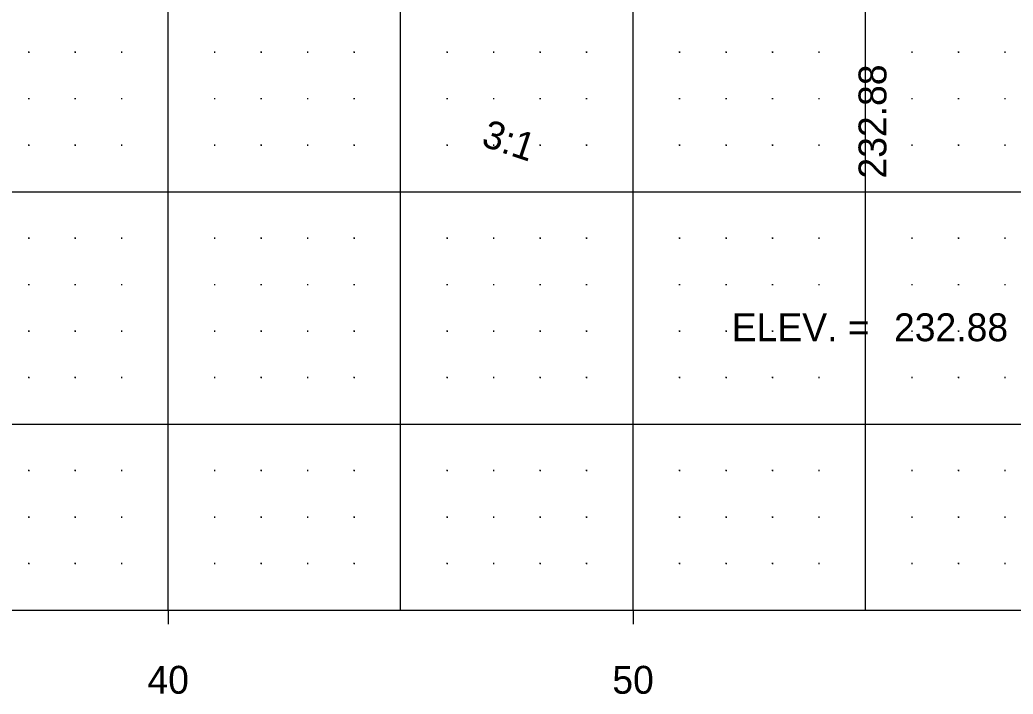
# Model space of a CAD drawing. Extents: x -80 to 80, y 222 to 253.
# Drawn here: x 36.81 to 58.18, y 224.19 to 238.7 of the extents above; entities that cross this region are included whole.
import ezdxf

# ---------------------------------------------------------------- set-up
doc = ezdxf.new("R2010")
doc.units = 0
for name, color, linetype in [('DSN_DRFT_XS Border Grid', 7, 'Continuous'), ('DSN_DRFT_XS Grid Annotations', 7, 'Continuous'), ('DSN_DRFT_XS Grid Major', 7, 'Continuous'), ('DSN_DRFT_XS Grid Minor', 7, 'Continuous'), ('DSN_RDWY_XS Annotation', 7, 'Continuous')]:
    doc.layers.add(name, color=color, linetype=linetype)

msp = doc.modelspace()

# ---------------------------------------------------------------- linework, layer by layer
at = {"layer": 'DSN_DRFT_XS Border Grid'}
msp.add_line((-77.5, 226), (77.5, 226), dxfattribs=at)
at = {"layer": 'DSN_DRFT_XS Grid Major'}
for p, q in [((40, 226), (40, 250.573)), ((45, 226), (45, 250.573)), ((50, 226), (50, 250.573)), ((55, 226), (55, 250.573)), ((-77.5, 235), (77.5, 235)), ((-77.5, 230), (77.5, 230)), ((40, 226), (40, 225.7)), ((50, 226), (50, 225.7))]:
    msp.add_line(p, q, dxfattribs=at)
at = {"layer": 'DSN_DRFT_XS Grid Minor'}
for p, q in [((37.012, 238), (36.988, 238)), ((37, 238.012), (37, 237.988)), ((38.012, 238), (37.988, 238)), ((38, 238.012), (38, 237.988)), ((39.012, 238), (38.988, 238)), ((39, 238.012), (39, 237.988)), ((41.012, 238), (40.988, 238)), ((41, 238.012), (41, 237.988)), ((42.012, 238), (41.988, 238)), ((42, 238.012), (42, 237.988)), ((43.012, 238), (42.988, 238)), ((43, 238.012), (43, 237.988)), ((44.012, 238), (43.988, 238)), ((44, 238.012), (44, 237.988)), ((46.012, 238), (45.988, 238)), ((46, 238.012), (46, 237.988)), ((47.012, 238), (46.988, 238)), ((47, 238.012), (47, 237.988)), ((48.012, 238), (47.988, 238)), ((48, 238.012), (48, 237.988)), ((49.012, 238), (48.988, 238)), ((49, 238.012), (49, 237.988)), ((51.012, 238), (50.988, 238)), ((51, 238.012), (51, 237.988)), ((52.012, 238), (51.988, 238)), ((52, 238.012), (52, 237.988)), ((53.012, 238), (52.988, 238)), ((53, 238.012), (53, 237.988)), ((54.012, 238), (53.988, 238)), ((54, 238.012), (54, 237.988)), ((56.012, 238), (55.988, 238)), ((56, 238.012), (56, 237.988)), ((57.012, 238), (56.988, 238)), ((57, 238.012), (57, 237.988)), ((58.012, 238), (57.988, 238)), ((58, 238.012), (58, 237.988)), ((37.012, 237), (36.988, 237)), ((37, 237.012), (37, 236.988)), ((38.012, 237), (37.988, 237)), ((38, 237.012), (38, 236.988)), ((39.012, 237), (38.988, 237)), ((39, 237.012), (39, 236.988)), ((41.012, 237), (40.988, 237)), ((41, 237.012), (41, 236.988)), ((42.012, 237), (41.988, 237)), ((42, 237.012), (42, 236.988)), ((43.012, 237), (42.988, 237)), ((43, 237.012), (43, 236.988)), ((44.012, 237), (43.988, 237)), ((44, 237.012), (44, 236.988)), ((46.012, 237), (45.988, 237)), ((46, 237.012), (46, 236.988)), ((47.012, 237), (46.988, 237)), ((47, 237.012), (47, 236.988)), ((48.012, 237), (47.988, 237)), ((48, 237.012), (48, 236.988)), ((49.012, 237), (48.988, 237)), ((49, 237.012), (49, 236.988)), ((51.012, 237), (50.988, 237)), ((51, 237.012), (51, 236.988)), ((52.012, 237), (51.988, 237)), ((52, 237.012), (52, 236.988)), ((53.012, 237), (52.988, 237)), ((53, 237.012), (53, 236.988)), ((54.012, 237), (53.988, 237)), ((54, 237.012), (54, 236.988)), ((56.012, 237), (55.988, 237)), ((56, 237.012), (56, 236.988)), ((57.012, 237), (56.988, 237)), ((57, 237.012), (57, 236.988)), ((58.012, 237), (57.988, 237)), ((58, 237.012), (58, 236.988)), ((37.012, 236), (36.988, 236)), ((37, 236.012), (37, 235.988)), ((38.012, 236), (37.988, 236)), ((38, 236.012), (38, 235.988)), ((39.012, 236), (38.988, 236)), ((39, 236.012), (39, 235.988)), ((41.012, 236), (40.988, 236)), ((41, 236.012), (41, 235.988)), ((42.012, 236), (41.988, 236)), ((42, 236.012), (42, 235.988)), ((43.012, 236), (42.988, 236)), ((43, 236.012), (43, 235.988)), ((44.012, 236), (43.988, 236)), ((44, 236.012), (44, 235.988)), ((46.012, 236), (45.988, 236)), ((46, 236.012), (46, 235.988)), ((47.012, 236), (46.988, 236)), ((47, 236.012), (47, 235.988)), ((48.012, 236), (47.988, 236)), ((48, 236.012), (48, 235.988)), ((49.012, 236), (48.988, 236)), ((49, 236.012), (49, 235.988)), ((51.012, 236), (50.988, 236)), ((51, 236.012), (51, 235.988)), ((52.012, 236), (51.988, 236)), ((52, 236.012), (52, 235.988)), ((53.012, 236), (52.988, 236)), ((53, 236.012), (53, 235.988)), ((54.012, 236), (53.988, 236)), ((54, 236.012), (54, 235.988)), ((56.012, 236), (55.988, 236)), ((56, 236.012), (56, 235.988)), ((57.012, 236), (56.988, 236)), ((57, 236.012), (57, 235.988)), ((58.012, 236), (57.988, 236)), ((58, 236.012), (58, 235.988)), ((37.012, 234), (36.988, 234)), ((37, 234.012), (37, 233.988)), ((38.012, 234), (37.988, 234)), ((38, 234.012), (38, 233.988)), ((39.012, 234), (38.988, 234)), ((39, 234.012), (39, 233.988)), ((41.012, 234), (40.988, 234)), ((41, 234.012), (41, 233.988)), ((42.012, 234), (41.988, 234)), ((42, 234.012), (42, 233.988)), ((43.012, 234), (42.988, 234)), ((43, 234.012), (43, 233.988)), ((44.012, 234), (43.988, 234)), ((44, 234.012), (44, 233.988)), ((46.012, 234), (45.988, 234)), ((46, 234.012), (46, 233.988)), ((47.012, 234), (46.988, 234)), ((47, 234.012), (47, 233.988)), ((48.012, 234), (47.988, 234)), ((48, 234.012), (48, 233.988)), ((49.012, 234), (48.988, 234)), ((49, 234.012), (49, 233.988)), ((51.012, 234), (50.988, 234)), ((51, 234.012), (51, 233.988)), ((52.012, 234), (51.988, 234)), ((52, 234.012), (52, 233.988)), ((53.012, 234), (52.988, 234)), ((53, 234.012), (53, 233.988)), ((54.012, 234), (53.988, 234)), ((54, 234.012), (54, 233.988)), ((56.012, 234), (55.988, 234)), ((56, 234.012), (56, 233.988)), ((57.012, 234), (56.988, 234)), ((57, 234.012), (57, 233.988)), ((58.012, 234), (57.988, 234)), ((58, 234.012), (58, 233.988)), ((37.012, 233), (36.988, 233)), ((37, 233.012), (37, 232.988)), ((38.012, 233), (37.988, 233)), ((38, 233.012), (38, 232.988)), ((39.012, 233), (38.988, 233)), ((39, 233.012), (39, 232.988)), ((41.012, 233), (40.988, 233)), ((41, 233.012), (41, 232.988)), ((42.012, 233), (41.988, 233)), ((42, 233.012), (42, 232.988)), ((43.012, 233), (42.988, 233)), ((43, 233.012), (43, 232.988)), ((44.012, 233), (43.988, 233)), ((44, 233.012), (44, 232.988)), ((46.012, 233), (45.988, 233)), ((46, 233.012), (46, 232.988)), ((47.012, 233), (46.988, 233)), ((47, 233.012), (47, 232.988)), ((48.012, 233), (47.988, 233)), ((48, 233.012), (48, 232.988)), ((49.012, 233), (48.988, 233)), ((49, 233.012), (49, 232.988)), ((51.012, 233), (50.988, 233)), ((51, 233.012), (51, 232.988)), ((52.012, 233), (51.988, 233)), ((52, 233.012), (52, 232.988)), ((53.012, 233), (52.988, 233)), ((53, 233.012), (53, 232.988)), ((54.012, 233), (53.988, 233)), ((54, 233.012), (54, 232.988)), ((56.012, 233), (55.988, 233)), ((56, 233.012), (56, 232.988)), ((57.012, 233), (56.988, 233)), ((57, 233.012), (57, 232.988)), ((58.012, 233), (57.988, 233)), ((58, 233.012), (58, 232.988)), ((37.012, 232), (36.988, 232)), ((37, 232.012), (37, 231.988)), ((38.012, 232), (37.988, 232)), ((38, 232.012), (38, 231.988)), ((39.012, 232), (38.988, 232)), ((39, 232.012), (39, 231.988)), ((41.012, 232), (40.988, 232)), ((41, 232.012), (41, 231.988)), ((42.012, 232), (41.988, 232)), ((42, 232.012), (42, 231.988)), ((43.012, 232), (42.988, 232)), ((43, 232.012), (43, 231.988)), ((44.012, 232), (43.988, 232)), ((44, 232.012), (44, 231.988)), ((46.012, 232), (45.988, 232)), ((46, 232.012), (46, 231.988)), ((47.012, 232), (46.988, 232)), ((47, 232.012), (47, 231.988)), ((48.012, 232), (47.988, 232)), ((48, 232.012), (48, 231.988)), ((49.012, 232), (48.988, 232)), ((49, 232.012), (49, 231.988)), ((51.012, 232), (50.988, 232)), ((51, 232.012), (51, 231.988)), ((52.012, 232), (51.988, 232)), ((52, 232.012), (52, 231.988)), ((53.012, 232), (52.988, 232)), ((53, 232.012), (53, 231.988)), ((54.012, 232), (53.988, 232)), ((54, 232.012), (54, 231.988)), ((56.012, 232), (55.988, 232)), ((56, 232.012), (56, 231.988)), ((57.012, 232), (56.988, 232)), ((57, 232.012), (57, 231.988)), ((58.012, 232), (57.988, 232)), ((58, 232.012), (58, 231.988)), ((37.012, 231), (36.988, 231)), ((37, 231.012), (37, 230.988)), ((38.012, 231), (37.988, 231)), ((38, 231.012), (38, 230.988)), ((39.012, 231), (38.988, 231)), ((39, 231.012), (39, 230.988)), ((41.012, 231), (40.988, 231)), ((41, 231.012), (41, 230.988)), ((42.012, 231), (41.988, 231)), ((42, 231.012), (42, 230.988)), ((43.012, 231), (42.988, 231)), ((43, 231.012), (43, 230.988)), ((44.012, 231), (43.988, 231)), ((44, 231.012), (44, 230.988)), ((46.012, 231), (45.988, 231)), ((46, 231.012), (46, 230.988)), ((47.012, 231), (46.988, 231)), ((47, 231.012), (47, 230.988)), ((48.012, 231), (47.988, 231)), ((48, 231.012), (48, 230.988)), ((49.012, 231), (48.988, 231)), ((49, 231.012), (49, 230.988)), ((51.012, 231), (50.988, 231)), ((51, 231.012), (51, 230.988)), ((52.012, 231), (51.988, 231)), ((52, 231.012), (52, 230.988)), ((53.012, 231), (52.988, 231)), ((53, 231.012), (53, 230.988)), ((54.012, 231), (53.988, 231)), ((54, 231.012), (54, 230.988)), ((56.012, 231), (55.988, 231)), ((56, 231.012), (56, 230.988)), ((57.012, 231), (56.988, 231)), ((57, 231.012), (57, 230.988)), ((58.012, 231), (57.988, 231)), ((58, 231.012), (58, 230.988)), ((37.012, 229), (36.988, 229)), ((37, 229.012), (37, 228.988)), ((38.012, 229), (37.988, 229)), ((38, 229.012), (38, 228.988)), ((39.012, 229), (38.988, 229)), ((39, 229.012), (39, 228.988)), ((41.012, 229), (40.988, 229)), ((41, 229.012), (41, 228.988)), ((42.012, 229), (41.988, 229)), ((42, 229.012), (42, 228.988)), ((43.012, 229), (42.988, 229)), ((43, 229.012), (43, 228.988)), ((44.012, 229), (43.988, 229)), ((44, 229.012), (44, 228.988)), ((46.012, 229), (45.988, 229)), ((46, 229.012), (46, 228.988)), ((47.012, 229), (46.988, 229)), ((47, 229.012), (47, 228.988)), ((48.012, 229), (47.988, 229)), ((48, 229.012), (48, 228.988)), ((49.012, 229), (48.988, 229)), ((49, 229.012), (49, 228.988)), ((51.012, 229), (50.988, 229)), ((51, 229.012), (51, 228.988)), ((52.012, 229), (51.988, 229)), ((52, 229.012), (52, 228.988)), ((53.012, 229), (52.988, 229)), ((53, 229.012), (53, 228.988)), ((54.012, 229), (53.988, 229)), ((54, 229.012), (54, 228.988)), ((56.012, 229), (55.988, 229)), ((56, 229.012), (56, 228.988)), ((57.012, 229), (56.988, 229)), ((57, 229.012), (57, 228.988)), ((58.012, 229), (57.988, 229)), ((58, 229.012), (58, 228.988)), ((37.012, 228), (36.988, 228)), ((37, 228.012), (37, 227.988)), ((38.012, 228), (37.988, 228)), ((38, 228.012), (38, 227.988)), ((39.012, 228), (38.988, 228)), ((39, 228.012), (39, 227.988)), ((41.012, 228), (40.988, 228)), ((41, 228.012), (41, 227.988)), ((42.012, 228), (41.988, 228)), ((42, 228.012), (42, 227.988)), ((43.012, 228), (42.988, 228)), ((43, 228.012), (43, 227.988)), ((44.012, 228), (43.988, 228)), ((44, 228.012), (44, 227.988)), ((46.012, 228), (45.988, 228)), ((46, 228.012), (46, 227.988)), ((47.012, 228), (46.988, 228)), ((47, 228.012), (47, 227.988)), ((48.012, 228), (47.988, 228)), ((48, 228.012), (48, 227.988)), ((49.012, 228), (48.988, 228)), ((49, 228.012), (49, 227.988)), ((51.012, 228), (50.988, 228)), ((51, 228.012), (51, 227.988)), ((52.012, 228), (51.988, 228)), ((52, 228.012), (52, 227.988)), ((53.012, 228), (52.988, 228)), ((53, 228.012), (53, 227.988)), ((54.012, 228), (53.988, 228)), ((54, 228.012), (54, 227.988)), ((56.012, 228), (55.988, 228)), ((56, 228.012), (56, 227.988)), ((57.012, 228), (56.988, 228)), ((57, 228.012), (57, 227.988)), ((58.012, 228), (57.988, 228)), ((58, 228.012), (58, 227.988)), ((37.012, 227), (36.988, 227)), ((37, 227.012), (37, 226.988)), ((38.012, 227), (37.988, 227)), ((38, 227.012), (38, 226.988)), ((39.012, 227), (38.988, 227)), ((39, 227.012), (39, 226.988)), ((41.012, 227), (40.988, 227)), ((41, 227.012), (41, 226.988)), ((42.012, 227), (41.988, 227)), ((42, 227.012), (42, 226.988)), ((43.012, 227), (42.988, 227)), ((43, 227.012), (43, 226.988)), ((44.012, 227), (43.988, 227)), ((44, 227.012), (44, 226.988)), ((46.012, 227), (45.988, 227)), ((46, 227.012), (46, 226.988)), ((47.012, 227), (46.988, 227)), ((47, 227.012), (47, 226.988)), ((48.012, 227), (47.988, 227)), ((48, 227.012), (48, 226.988)), ((49.012, 227), (48.988, 227)), ((49, 227.012), (49, 226.988)), ((51.012, 227), (50.988, 227)), ((51, 227.012), (51, 226.988)), ((52.012, 227), (51.988, 227)), ((52, 227.012), (52, 226.988)), ((53.012, 227), (52.988, 227)), ((53, 227.012), (53, 226.988)), ((54.012, 227), (53.988, 227)), ((54, 227.012), (54, 226.988)), ((56.012, 227), (55.988, 227)), ((56, 227.012), (56, 226.988)), ((57.012, 227), (56.988, 227)), ((57, 227.012), (57, 226.988)), ((58.012, 227), (57.988, 227)), ((58, 227.012), (58, 226.988))]:
    msp.add_line(p, q, dxfattribs=at)

# ---------------------------------------------------------------- texts
at = {"layer": 'DSN_DRFT_XS Grid Annotations'}
for s, p in [('40', (39.555, 224.2)), ('50', (49.555, 224.2))]:
    msp.add_text(s, height=0.6, dxfattribs=at).set_placement(p)
at = {"layer": 'DSN_RDWY_XS Annotation'}
for s, rotation, p in [('232.88', 90, (55.451, 235.284)), ('3:1', 341.5651, (46.711, 235.997))]:
    msp.add_text(s, height=0.6, rotation=rotation, dxfattribs=at).set_placement(p)
for s, p in [('ELEV. = ', (52.123, 231.784)), ('232.88', (55.614, 231.784))]:
    msp.add_text(s, height=0.6, dxfattribs=at).set_placement(p)

doc.saveas('drawing.dxf')
